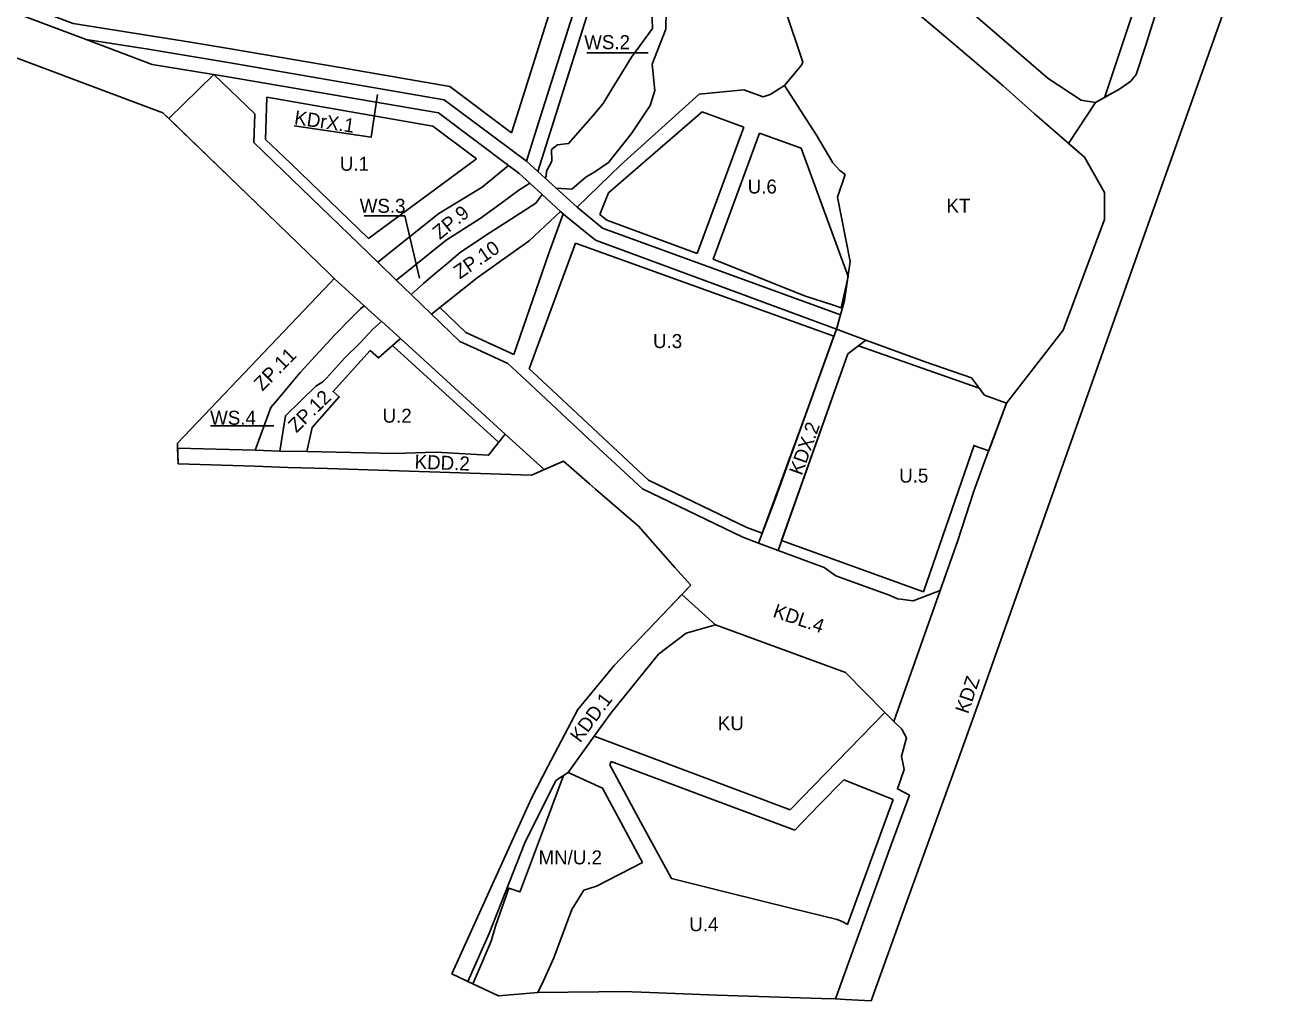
# Model space of a CAD drawing. Extents: x 7422426 to 7423369, y 5542157 to 5542988.
# Drawn here: x 7422842.1 to 7423201.2, y 5542157 to 5542435.8 of the extents above; entities that cross this region are included whole.
import ezdxf

# ---------------------------------------------------------------- set-up
doc = ezdxf.new("R2010")
doc.units = 0
for name, color, linetype in [('GRANICA OBSZARU OBJĘTEGO PLANEM', 7, 'Continuous'), ('LINIE ROZGRANICZAJĄCE TERENY O RÓŻNYM PRZEZNACZENIU LUB RÓŻNYCH ZASADACH ZAGOSPODAROWANIA', 7, 'Continuous'), ('NIEPRZEKRACZALNA LINIA ZABUDOWY', 7, 'Continuous'), ('OBOWIĄZUJĄCA LINIA ZABUDOWY', 7, 'Continuous'), ('OZNACZENIA TERENÓW', 7, 'Continuous')]:
    doc.layers.add(name, color=color, linetype=linetype)

msp = doc.modelspace()

# ---------------------------------------------------------------- linework, layer by layer
at = {"layer": 'GRANICA OBSZARU OBJĘTEGO PLANEM'}
for p, q in [((7422928.98, 5542364.73), (7422911.18, 5542381.94)), ((7422885.53, 5542316.31), (7422929.22, 5542362.23)), ((7422885.77, 5542310.44), (7422885.53, 5542316.31)), ((7422907.68, 5542309.74), (7422885.77, 5542310.44)), ((7422917.04, 5542309.43), (7422907.68, 5542309.74)), ((7422928.43, 5542309.07), (7422917.04, 5542309.43)), ((7422986.66, 5542307.18), (7422928.43, 5542309.07)), ((7422987.33, 5542307.48), (7422986.66, 5542307.18)), ((7423004.95, 5542303.24), (7423003.21, 5542304.75)), ((7423032.1, 5542275.75), (7423027.57, 5542280.87)), ((7423017.96, 5542260.91), (7423032.1, 5542275.75)), ((7422991.35, 5542223.97), (7422997.97, 5542236.62)), ((7422986.62, 5542214.95), (7422991.35, 5542223.97)), ((7423108.16, 5542225.13), (7423093.84, 5542185.41)), ((7422963.87, 5542164.68), (7422986.62, 5542214.95)), ((7423093.84, 5542185.41), (7423083.61, 5542157)), ((7422968.47, 5542162.52), (7422963.87, 5542164.68)), ((7423020.44, 5542159.35), (7423012.94, 5542159.63)), ((7423039.7, 5542158.62), (7423020.44, 5542159.35)), ((7423069.36, 5542157.71), (7423039.7, 5542158.62)), ((7423073.41, 5542157.58), (7423069.36, 5542157.71))]:
    msp.add_line(p, q, dxfattribs=at)
for points in [[(7423201.18, 5542487.24), (7423190.43, 5542456.94), (7423177.58, 5542420.71), (7423161.25, 5542374.63), (7423114.75, 5542243.43), (7423108.16, 5542225.13)], [(7422911.18, 5542381.94), (7422881.36, 5542410.77), (7422824.52, 5542432.08)], [(7422929.22, 5542362.23), (7422930.35, 5542363.41), (7422928.98, 5542364.73)], [(7423003.21, 5542304.75), (7422995.79, 5542311.19), (7422987.33, 5542307.48)], [(7423027.57, 5542280.87), (7423017.22, 5542292.6), (7423004.95, 5542303.24)], [(7422997.97, 5542236.62), (7422999.89, 5542240.29), (7423010.26, 5542252.82), (7423017.96, 5542260.91)], [(7422988.47, 5542159.37), (7422977.25, 5542158.4), (7422968.47, 5542162.52)], [(7423012.94, 5542159.63), (7423005.91, 5542159.55), (7422988.47, 5542159.37)], [(7423083.61, 5542157), (7423076.35, 5542157.41), (7423073.41, 5542157.58)]]:
    msp.add_lwpolyline(points, dxfattribs=at)
at = {"layer": 'LINIE ROZGRANICZAJĄCE TERENY O RÓŻNYM PRZEZNACZENIU LUB RÓŻNYCH ZASADACH ZAGOSPODAROWANIA'}
for p, q in [((7422859.53, 5542431.67), (7422878.38, 5542424.57)), ((7422895.92, 5542421.72), (7422883.06, 5542409.13)), ((7422895.92, 5542421.72), (7422907.62, 5542410.43)), ((7422907.62, 5542410.43), (7422907.34, 5542402.28)), ((7422942.78, 5542368.04), (7422907.34, 5542402.28)), ((7422990.53, 5542392.1), (7422993.56, 5542389.33)), ((7422928.98, 5542364.73), (7422911.18, 5542381.94)), ((7422885.53, 5542316.31), (7422929.22, 5542362.23)), ((7422938.89, 5542355.63), (7422943.84, 5542351.14)), ((7422966.22, 5542345.42), (7422958.12, 5542353.25)), ((7423116.02, 5542330.09), (7423122.27, 5542327.74)), ((7422885.6, 5542314.53), (7422885.53, 5542316.31)), ((7422885.77, 5542310.44), (7422885.59, 5542314.91)), ((7422907.68, 5542309.74), (7422885.77, 5542310.44)), ((7422917.04, 5542309.43), (7422907.68, 5542309.74)), ((7422928.43, 5542309.07), (7422917.04, 5542309.43)), ((7422986.66, 5542307.18), (7422928.43, 5542309.07)), ((7422987.33, 5542307.48), (7422986.66, 5542307.18)), ((7423004.95, 5542303.24), (7423003.21, 5542304.75)), ((7423046.96, 5542289.49), (7423018.32, 5542303.26)), ((7423046.96, 5542289.49), (7423051.42, 5542287.81)), ((7423032.1, 5542275.75), (7423027.57, 5542280.87)), ((7423076.28, 5542250.86), (7423039.19, 5542264.41)), ((7423087.52, 5542239.37), (7423076.28, 5542250.86)), ((7423087.52, 5542239.37), (7423060.5, 5542211.63)), ((7422991.35, 5542223.97), (7422997.97, 5542236.62)), ((7422986.62, 5542214.95), (7422991.35, 5542223.97)), ((7423108.16, 5542225.13), (7423093.84, 5542185.41)), ((7422963.87, 5542164.68), (7422986.62, 5542214.95)), ((7423093.84, 5542185.41), (7423083.61, 5542157)), ((7422968.47, 5542162.52), (7422963.87, 5542164.68)), ((7423020.44, 5542159.35), (7423012.94, 5542159.63)), ((7423039.7, 5542158.62), (7423020.44, 5542159.35)), ((7423069.36, 5542157.71), (7423039.7, 5542158.62)), ((7423073.41, 5542157.58), (7423069.36, 5542157.71))]:
    msp.add_line(p, q, dxfattribs=at)
for points in [[(7423144.59, 5542398.03), (7423130.24, 5542410.43), (7423121.3, 5542418.45), (7423104.3, 5542432.93), (7423092.28, 5542443.17), (7423086.26, 5542448.39), (7423071.89, 5542470.3), (7423063.04, 5542496.35), (7423060.47, 5542505.88), (7423059.44, 5542516.76), (7423060.83, 5542528.59), (7423063.4, 5542537.59), (7423064.24, 5542540.58), (7423071.96, 5542562.51), (7423076.84, 5542573.46), (7423081.97, 5542581.66), (7423087.85, 5542587.89), (7423093.39, 5542591.88), (7423100.66, 5542595.42), (7423108.86, 5542597.47), (7423117.92, 5542597.74), (7423128.28, 5542596.1), (7423137.46, 5542593.45)], [(7422988.43, 5542394), (7422991.92, 5542404.83), (7423012.86, 5542471.45), (7423026.46, 5542529.73)], [(7423110.52, 5542512.17), (7423101.05, 5542504.62), (7423100.57, 5542502.53), (7423096.85, 5542483.36), (7423093.52, 5542466.18), (7423093.68, 5542462.25), (7423094.64, 5542457.86), (7423097.2, 5542452.8), (7423100.2, 5542449.94), (7423134.17, 5542420.54), (7423143.55, 5542414.35), (7423147.72, 5542413.7), (7423151.91, 5542416.05)], [(7423201.18, 5542487.24), (7423190.43, 5542456.94), (7423177.58, 5542420.71), (7423161.25, 5542374.63), (7423114.75, 5542243.43), (7423108.16, 5542225.13)], [(7423138.42, 5542348.62), (7423138.42, 5542348.62), (7423150.26, 5542380.3), (7423150.23, 5542387.98), (7423144.59, 5542398.03), (7423139.98, 5542402), (7423147.72, 5542413.7), (7423154.32, 5542417.39), (7423157.8, 5542419.8), (7423159.27, 5542421.67), (7423161.94, 5542429.82), (7423167.46, 5542447.53), (7423177.78, 5542477.28), (7423181.5, 5542488)], [(7423047.58, 5542470.88), (7423048.58, 5542471.61), (7423064.13, 5542425.21), (7423063.72, 5542424.34)], [(7422985.19, 5542396.96), (7422988.11, 5542406.04), (7423005.58, 5542461.55)], [(7422859.52, 5542431.68), (7422819.5, 5542446.77), (7422735.96, 5542460.38)], [(7422990.53, 5542392.1), (7422990.86, 5542392.67), (7422990.93, 5542394.03), (7422992.49, 5542396.95), (7422992.33, 5542400.25), (7422994.09, 5542401.6), (7422997.26, 5542401.95), (7423004.12, 5542409.9), (7423007.09, 5542413.39), (7423009.91, 5542417.99), (7423011.13, 5542420.01), (7423015.18, 5542426.64), (7423021.21, 5542434.85), (7423020.6, 5542450.91)], [(7423025.19, 5542444.95), (7423025.04, 5542434.67), (7423021.11, 5542424.62), (7423021.86, 5542417.09), (7423020.55, 5542412.81), (7423015.25, 5542404.81), (7423008.64, 5542396.59), (7423004.49, 5542393.71), (7423002.24, 5542392.41), (7422998.16, 5542388.91), (7422993.59, 5542389.24)], [(7422911.18, 5542381.94), (7422883.06, 5542409.13), (7422881.36, 5542410.77), (7422824.52, 5542432.08)], [(7422859.52, 5542431.68), (7422877.21, 5542428.94), (7422900.08, 5542425.1), (7422961.71, 5542414.49), (7422985.19, 5542396.96), (7422988.43, 5542394)], [(7422878.38, 5542424.57), (7422878.38, 5542424.57), (7422899.41, 5542421.15), (7422960.08, 5542410.71), (7422980.07, 5542395.72)], [(7422999.68, 5542383.77), (7423012.17, 5542395.92), (7423034.52, 5542416.03), (7423047.26, 5542417.28), (7423052.82, 5542415.33), (7423054.81, 5542416), (7423058.86, 5542418.57), (7423063.72, 5542424.34)], [(7423058.86, 5542418.57), (7423067.98, 5542404.4), (7423072.65, 5542396.5), (7423074.71, 5542394.3), (7423076.21, 5542393.1), (7423074.02, 5542386.61), (7423077.6, 5542368.3), (7423076, 5542357.1), (7423074.84, 5542353), (7423073.69, 5542348.89), (7423082.08, 5542345.82)], [(7422980.07, 5542395.72), (7422972.55, 5542389.46), (7422960.15, 5542381.96), (7422942.78, 5542368.04)], [(7422980.07, 5542395.72), (7422983.06, 5542393.48), (7422986.16, 5542390.63)], [(7422988.43, 5542394), (7422990.54, 5542392.08)], [(7422986.16, 5542390.63), (7422983.05, 5542388.65), (7422977.88, 5542384.79), (7422972.04, 5542380.58), (7422962.33, 5542374.35), (7422949.61, 5542364.21), (7422948.02, 5542362.95)], [(7422986.16, 5542390.63), (7422989.68, 5542387.36)], [(7422993.56, 5542389.33), (7422999.68, 5542383.77)], [(7422952.32, 5542358.84), (7422954.89, 5542361.12), (7422955.85, 5542361.96), (7422958.59, 5542364.31), (7422962.49, 5542367.63), (7422966.3, 5542370.87), (7422969.76, 5542373.21), (7422974.87, 5542376.52), (7422980.91, 5542380.43), (7422987.91, 5542384.95), (7422989.68, 5542387.36)], [(7422989.68, 5542387.36), (7422994.97, 5542382.58)], [(7422985.94, 5542374.19), (7422994.97, 5542382.58), (7422994.97, 5542382.58), (7422994.97, 5542382.58)], [(7422994.97, 5542382.58), (7422996.43, 5542381.25)], [(7422999.68, 5542383.77), (7423006.9, 5542377.83), (7423074.84, 5542353)], [(7422996.43, 5542381.25), (7423004.89, 5542374.31), (7423073.69, 5542348.89)], [(7422985.94, 5542374.19), (7422971.12, 5542363.56), (7422958.12, 5542353.25)], [(7422942.78, 5542368.04), (7422948.02, 5542362.95), (7422952.32, 5542358.84), (7422958.12, 5542353.25)], [(7422929.22, 5542362.23), (7422930.35, 5542363.41), (7422928.98, 5542364.73)], [(7422930.35, 5542363.41), (7422938.89, 5542355.63)], [(7422907.71, 5542314.33), (7422912.24, 5542326.57), (7422914.39, 5542329.08), (7422920.61, 5542336.57), (7422930.43, 5542347.2), (7422935.29, 5542352.2), (7422937.82, 5542354.74), (7422938.89, 5542355.63)], [(7422943.84, 5542351.14), (7422941.37, 5542348.9), (7422937.66, 5542344.91), (7422933.23, 5542340.64), (7422928.09, 5542334.97), (7422927.1, 5542333.88), (7422925.11, 5542332.66), (7422920.7, 5542328.34), (7422916.41, 5542324.17), (7422914.78, 5542314.11)], [(7422943.81, 5542351.18), (7422949.23, 5542346.25)], [(7422949.23, 5542346.25), (7422942.92, 5542340.73), (7422940.58, 5542342.81), (7422930, 5542331.15), (7422931.75, 5542329.56), (7422924.04, 5542320.82), (7422922.49, 5542313.94)], [(7422949.23, 5542346.25), (7422979.18, 5542318.92)], [(7423073.69, 5542348.89), (7423056.1, 5542300.02), (7423051.42, 5542287.81)], [(7423112.93, 5542302.64), (7423116.37, 5542312.05), (7423122.27, 5542327.74), (7423138.42, 5542348.62)], [(7422971.03, 5542343.21), (7422966.22, 5542345.42)], [(7422984.82, 5542334.52), (7422979.88, 5542339.15), (7422971.03, 5542343.21)], [(7423082.08, 5542345.82), (7423076.99, 5542341.84), (7423057.1, 5542285.67), (7423057.1, 5542285.67)], [(7423082.08, 5542345.82), (7423099.01, 5542339.61), (7423112.27, 5542335)], [(7423005.77, 5542314.96), (7422984.82, 5542334.52)], [(7423112.27, 5542335), (7423116.02, 5542330.09)], [(7422959.34, 5542313.78), (7422974.39, 5542312.92), (7422979.18, 5542318.92)], [(7422979.18, 5542318.92), (7422990.31, 5542308.79)], [(7422914.78, 5542314.11), (7422907.71, 5542314.33), (7422885.59, 5542314.91)], [(7422922.49, 5542313.94), (7422914.78, 5542314.11)], [(7422959.34, 5542313.78), (7422947.64, 5542313.41), (7422922.49, 5542313.94)], [(7423018.32, 5542303.26), (7423005.77, 5542314.96)], [(7423003.21, 5542304.75), (7422995.79, 5542311.19), (7422990.31, 5542308.79), (7422987.33, 5542307.48)], [(7423027.57, 5542280.87), (7423017.22, 5542292.6), (7423004.95, 5542303.24)], [(7423112.93, 5542302.64), (7423108.35, 5542288.57), (7423103.29, 5542274.26), (7423090.07, 5542236.86)], [(7423092.03, 5542271.8), (7423091.2, 5542271.92), (7423089.24, 5542272.72), (7423089.04, 5542272.84), (7423073.5, 5542278.42), (7423070.26, 5542280.8), (7423057.1, 5542285.67), (7423051.42, 5542287.81)], [(7423017.96, 5542260.91), (7423029.57, 5542273.09), (7423032.1, 5542275.75)], [(7423103.29, 5542274.26), (7423103.29, 5542274.26), (7423095.59, 5542271.31), (7423092.03, 5542271.8)], [(7423029.57, 5542273.09), (7423039.19, 5542264.41)], [(7423039.19, 5542264.41), (7423030.81, 5542262.11), (7423022.92, 5542256.09), (7423009.28, 5542239.17), (7423004.54, 5542232.59)], [(7422997.97, 5542236.62), (7422999.89, 5542240.29), (7423010.26, 5542252.82), (7423017.96, 5542260.91)], [(7423073.41, 5542157.58), (7423084.48, 5542188.15), (7423089.33, 5542201.57), (7423094.54, 5542215.8), (7423091.11, 5542217.54), (7423093.04, 5542223.12), (7423092.34, 5542226.95), (7423093.69, 5542232.18), (7423092.36, 5542234.61), (7423090.07, 5542236.86), (7423087.52, 5542239.37)], [(7423004.54, 5542232.59), (7422997.09, 5542222.24)], [(7423004.54, 5542232.59), (7423060.5, 5542211.63)], [(7422997.09, 5542222.24), (7423006.96, 5542217.76), (7423018.31, 5542196.56), (7423005.21, 5542189.74), (7423001.63, 5542188.67), (7422998.14, 5542183.07), (7422993, 5542169.31), (7422989.94, 5542162.58), (7422988.47, 5542159.37)], [(7422997.09, 5542222.24), (7422993.57, 5542220.01)], [(7422968.47, 5542162.52), (7422974.54, 5542176.29), (7422984.76, 5542202.2), (7422993.57, 5542220.01)], [(7422988.47, 5542159.37), (7422977.25, 5542158.4), (7422968.47, 5542162.52)], [(7423012.94, 5542159.63), (7423005.91, 5542159.55), (7422988.47, 5542159.37)], [(7423083.61, 5542157), (7423076.35, 5542157.41), (7423073.41, 5542157.58)]]:
    msp.add_lwpolyline(points, dxfattribs=at)
at = {"layer": 'NIEPRZEKRACZALNA LINIA ZABUDOWY'}
for p, q in [((7423150.22, 5542414.99), (7423175.3, 5542490.18)), ((7422911.07, 5542415.2), (7422910.67, 5542403.16)), ((7422958.45, 5542406.93), (7422911.07, 5542415.2)), ((7423047.25, 5542406.68), (7423035.37, 5542410.99)), ((7422970.99, 5542397.64), (7422958.45, 5542406.93)), ((7423033.99, 5542370.59), (7423047.25, 5542406.68)), ((7422940.12, 5542374.79), (7422970.99, 5542397.64)), ((7422999.17, 5542373.51), (7422986.03, 5542337.55)), ((7423072.93, 5542346.93), (7422999.17, 5542373.51)), ((7422977.16, 5542316.71), (7422947.2, 5542344.03)), ((7423114.47, 5542332.06), (7423080.01, 5542344.16)), ((7423009.37, 5542225.44), (7423009.04, 5542224.41)), ((7423075.79, 5542220.16), (7423068.83, 5542213.01)), ((7423089.94, 5542214.52), (7423075.79, 5542220.16)), ((7423068.83, 5542213.01), (7423061.81, 5542205.8))]:
    msp.add_line(p, q, dxfattribs=at)
for points in [[(7422726.51, 5542465.58), (7422731.44, 5542464.31), (7422736.44, 5542463.34), (7422778.36, 5542456.51), (7422820.28, 5542449.69), (7422838.01, 5542443), (7422855.74, 5542436.31), (7422889.3, 5542430.97), (7422900.75, 5542429.04), (7422932.04, 5542423.65), (7422963.33, 5542418.26), (7422980.98, 5542405.05)], [(7422980.98, 5542405.05), (7422982.5, 5542409.77), (7422992.74, 5542442.33), (7422998.99, 5542462.03)], [(7423035.37, 5542410.99), (7423008.65, 5542387.84), (7423006.15, 5542381.67)], [(7422910.67, 5542403.16), (7422917.95, 5542396.24), (7422940.12, 5542374.79)], [(7422981.58, 5542341.67), (7422991.54, 5542370.33), (7422995.7, 5542381.92)], [(7423006.15, 5542381.67), (7423008.16, 5542380.03), (7423033.99, 5542370.59)], [(7422960.47, 5542355.15), (7422967.94, 5542347.93), (7422981.58, 5542341.67)], [(7423052.48, 5542290.61), (7423064.9, 5542324.46), (7423072.93, 5542346.93)], [(7423080.06, 5542344.2), (7423076.99, 5542341.84), (7423058.04, 5542288.51), (7423098.55, 5542273.84)], [(7422986.03, 5542337.55), (7422988.24, 5542335.51), (7423004.14, 5542320.64), (7423020.03, 5542305.76), (7423048.14, 5542292.25), (7423052.48, 5542290.61)], [(7423112.88, 5542315.73), (7423117.2, 5542314.18), (7423122.27, 5542327.74), (7423116.02, 5542330.09), (7423114.47, 5542332.06)], [(7423009.04, 5542224.41), (7423017.82, 5542208.2), (7423026.6, 5542191.99), (7423042.65, 5542188.01), (7423060.69, 5542183.53), (7423073.93, 5542180.26), (7423075.52, 5542179.62), (7423076.92, 5542178.86)], [(7423061.81, 5542205.8), (7423035.59, 5542215.62), (7423009.37, 5542225.44)], [(7422995.82, 5542221.44), (7422990.64, 5542207.61), (7422983.5, 5542188.56), (7422983.34, 5542188.13), (7422980.15, 5542189.23), (7422976.36, 5542178.3)], [(7422976.36, 5542178.3), (7422975.18, 5542174.1), (7422970.93, 5542164.29), (7422969.88, 5542161.86)]]:
    msp.add_lwpolyline(points, dxfattribs=at)
msp.add_lwpolyline([(7423051.72, 5542404.93), (7423038.56, 5542368.92), (7423064.58, 5542358.42), (7423072.86, 5542355.75), (7423075.06, 5542355.06), (7423077.11, 5542363.94), (7423063.61, 5542400.61)], close=True, dxfattribs=at)
at = {"layer": 'OBOWIĄZUJĄCA LINIA ZABUDOWY'}
for p, q in [((7423098.53, 5542273.85), (7423113.09, 5542315.78)), ((7423076.92, 5542178.86), (7423089.94, 5542214.52))]:
    msp.add_line(p, q, dxfattribs=at)
at = {"layer": 'OZNACZENIA TERENÓW'}
for p, q in [((7423002.42, 5542427.93), (7423020.01, 5542427.93)), ((7422895.02, 5542321.3), (7422913.12, 5542321.3))]:
    msp.add_line(p, q, dxfattribs=at)
for points in [[(7422918.93, 5542407.03), (7422940.89, 5542403.76), (7422942.7, 5542415.96)], [(7422938.88, 5542381.3), (7422950.51, 5542381.3), (7422954.63, 5542363.48)]]:
    msp.add_lwpolyline(points, dxfattribs=at)

# ---------------------------------------------------------------- texts
for s, p in [('WS.2', (7423001.7, 5542428.93)), ('U.1', (7422931.93, 5542394.19)), ('U.6', (7423048.37, 5542387.69)), ('WS.3', (7422937.6, 5542382.17)), ('KT', (7423105.14, 5542382.21)), ('U.3', (7423021.35, 5542343.52)), ('WS.4', (7422894.89, 5542321.61)), ('U.2', (7422944.13, 5542322.2)), ('U.5', (7423091.63, 5542305.09)), ('KU', (7423039.85, 5542234.33)), ('MN/U.2', (7422988.65, 5542196)), ('U.4', (7423031.7, 5542176.89))]:
    msp.add_text(s, height=4, dxfattribs=at).set_placement(p)
for s, rotation, p in [('KDrX.1', 351.6363, (7422918.75, 5542407.51)), ('ZP.9', 39.2265, (7422960.48, 5542374.36)), ('ZP.10', 34.4679, (7422966.18, 5542363.11)), ('ZP.11', 45.3167, (7422909.82, 5542331.03)), ('ZP.12', 44.112, (7422919.52, 5542319.1)), ('KDX.2', 70.2511, (7423063.84, 5542306.92)), ('KDD.2', 357.9008, (7422953.22, 5542309.08)), ('KDL.4', 341.2035, (7423055.32, 5542266.79)), ('KDZ', 71.1624, (7423111.3, 5542238.79)), ('KDD.1', 53.2007, (7423000.54, 5542230.53))]:
    msp.add_text(s, height=4, rotation=rotation, dxfattribs=at).set_placement(p)

doc.saveas('drawing.dxf')
